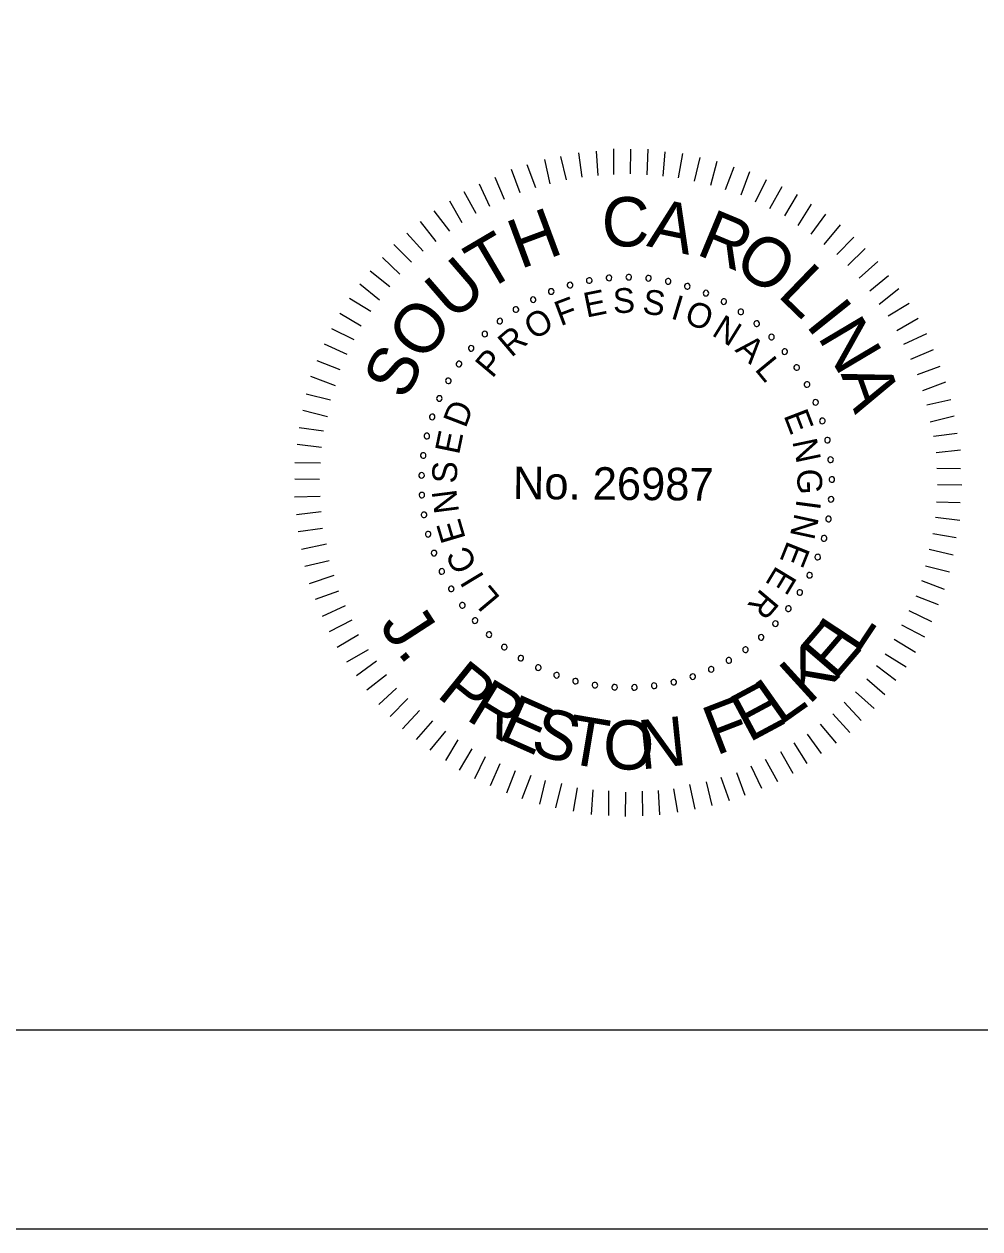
# Model space of a CAD drawing. Extents: x -125.5 to -89.4, y -5.1 to 16.9.
# Drawn here: x -102.74 to -100.338, y -5.066 to -2.039 of the extents above; entities that cross this region are included whole.
import ezdxf

# ---------------------------------------------------------------- set-up
doc = ezdxf.new("R2010")
doc.units = 0
for name, color, linetype in [('BR_BORDER LINES', 7, 'Continuous'), ('BR_TEXT', 7, 'Continuous'), ('Level 31', 7, 'Continuous')]:
    doc.layers.add(name, color=color, linetype=linetype)

msp = doc.modelspace()

# ---------------------------------------------------------------- linework, layer by layer
at = {"layer": 'BR_BORDER LINES'}
msp.add_line((-123.6994, -4.5662), (-90.0334, -4.5662), dxfattribs=at)
at = {"layer": 'BR_TEXT'}
for p, q in [((-101.2977, -2.419), (-101.3015, -2.3581)), ((-101.2582, -2.4168), (-101.2576, -2.3524)), ((-101.2161, -2.4146), (-101.2156, -2.3528)), ((-101.1741, -2.4175), (-101.1718, -2.3531)), ((-101.1338, -2.4204), (-101.129, -2.3595)), ((-101.418, -2.4404), (-101.4312, -2.3793)), ((-101.3767, -2.4304), (-101.3908, -2.3711)), ((-101.3372, -2.423), (-101.3461, -2.362)), ((-101.0952, -2.425), (-101.0844, -2.3642)), ((-101.0549, -2.4331), (-101.0407, -2.374)), ((-101.0138, -2.4437), (-100.9979, -2.3829)), ((-101.4937, -2.4629), (-101.5147, -2.4044)), ((-101.4541, -2.4504), (-101.476, -2.3927)), ((-100.977, -2.4543), (-100.9551, -2.397)), ((-100.9376, -2.4675), (-100.9157, -2.4093)), ((-101.5695, -2.4966), (-101.5957, -2.4406)), ((-101.5325, -2.4798), (-101.556, -2.4238)), ((-100.9017, -2.485), (-100.8738, -2.4294)), ((-100.8658, -2.5024), (-100.8345, -2.4469)), ((-101.604, -2.5144), (-101.6344, -2.46)), ((-100.8282, -2.5208), (-100.796, -2.467)), ((-101.6704, -2.5593), (-101.7095, -2.5083)), ((-101.6394, -2.5381), (-101.6698, -2.4838)), ((-100.795, -2.5451), (-100.761, -2.4913)), ((-101.7041, -2.5847), (-101.744, -2.5346)), ((-100.7617, -2.5668), (-100.7252, -2.5165)), ((-101.7369, -2.6094), (-101.7786, -2.5644)), ((-100.7293, -2.5928), (-100.6886, -2.5434)), ((-101.7663, -2.6366), (-101.8106, -2.5925)), ((-100.6977, -2.618), (-100.6545, -2.5737)), ((-100.6697, -2.6456), (-100.6264, -2.6022)), ((-101.7958, -2.6673), (-101.8392, -2.6248)), ((-101.8209, -2.6988), (-101.8704, -2.6598)), ((-100.6416, -2.6768), (-100.594, -2.6351)), ((-101.8469, -2.732), (-101.8964, -2.6922)), ((-100.6144, -2.7088), (-100.5677, -2.6705)), ((-100.5906, -2.7424), (-100.5414, -2.7033)), ((-101.8686, -2.761), (-101.9224, -2.728)), ((-100.5686, -2.7718), (-100.516, -2.7396)), ((-101.893, -2.7977), (-101.9467, -2.7656)), ((-100.5466, -2.8089), (-100.4931, -2.7776)), ((-101.9104, -2.8319), (-101.9668, -2.804)), ((-101.9279, -2.8687), (-101.9852, -2.8433)), ((-100.5288, -2.8433), (-100.4711, -2.8164)), ((-100.5111, -2.8804), (-100.4543, -2.856)), ((-101.9454, -2.9072), (-102.0035, -2.8852)), ((-100.4943, -2.9192), (-100.4374, -2.8982)), ((-101.9577, -2.9474), (-102.0193, -2.9246)), ((-100.4809, -2.9596), (-100.4232, -2.9378)), ((-101.97, -2.9833), (-102.0308, -2.9682)), ((-100.4708, -2.9957), (-100.4107, -2.9816)), ((-101.9772, -3.0253), (-102.0397, -3.0094)), ((-100.4626, -3.0378), (-100.4024, -3.0229)), ((-101.9878, -3.0613), (-102.0487, -3.0531)), ((-100.4543, -3.074), (-100.3951, -3.0667)), ((-101.9925, -3.1024), (-102.0542, -3.0951)), ((-100.4478, -3.1152), (-100.3868, -3.1088)), ((-101.9954, -3.1419), (-102.0597, -3.1414)), ((-100.4464, -3.1547), (-100.3863, -3.1552)), ((-101.9974, -3.183), (-102.06, -3.1825)), ((-100.4442, -3.1959), (-100.3833, -3.1964)), ((-101.9961, -3.226), (-102.0604, -3.2272)), ((-100.4471, -3.2388), (-100.3871, -3.241)), ((-101.9938, -3.2646), (-102.0556, -3.2718)), ((-100.4492, -3.2774), (-100.3883, -3.2856)), ((-101.9898, -3.3058), (-102.0509, -3.3148)), ((-100.4564, -3.3185), (-100.3972, -3.3284)), ((-101.9799, -3.3454), (-102.0426, -3.3586)), ((-100.4653, -3.3579), (-100.4053, -3.3721)), ((-101.9733, -3.3875), (-102.0344, -3.4016)), ((-100.4742, -3.3999), (-100.4143, -3.415)), ((-101.9616, -3.4245), (-102.0236, -3.4454)), ((-100.4848, -3.4367), (-100.4275, -3.4586)), ((-101.95, -3.4632), (-102.0085, -3.4842)), ((-100.4989, -3.4752), (-100.4424, -3.4971)), ((-101.9331, -3.5003), (-101.9908, -3.5272)), ((-101.9162, -3.5364), (-101.9731, -3.566)), ((-100.5163, -3.512), (-100.4599, -3.5399)), ((-100.5346, -3.5479), (-100.4774, -3.5784)), ((-101.8994, -3.5735), (-101.9537, -3.6048)), ((-100.553, -3.5846), (-100.5, -3.6168)), ((-101.8756, -3.6106), (-101.93, -3.6419)), ((-100.5756, -3.6213), (-100.5235, -3.6535)), ((-101.8544, -3.6399), (-101.9045, -3.6764)), ((-100.5981, -3.6503), (-100.5495, -3.6876)), ((-101.829, -3.6736), (-101.8791, -3.7127)), ((-100.6224, -3.6836), (-100.5764, -3.7234)), ((-101.8043, -3.7073), (-101.8485, -3.7481)), ((-100.6502, -3.7168), (-100.6033, -3.7584)), ((-101.7754, -3.7333), (-101.8204, -3.7784)), ((-100.6787, -3.7423), (-100.6362, -3.7882)), ((-101.7465, -3.7636), (-101.7889, -3.8095)), ((-100.7073, -3.7721), (-100.6648, -3.8188)), ((-101.714, -3.7895), (-101.7548, -3.8364)), ((-100.7392, -3.7976), (-100.6993, -3.8452)), ((-101.6808, -3.8156), (-101.7207, -3.8633)), ((-101.6501, -3.8373), (-101.6814, -3.8894)), ((-100.8057, -3.8443), (-100.7727, -3.8969)), ((-100.772, -3.8231), (-100.7364, -3.8714)), ((-101.6151, -3.8599), (-101.6464, -3.9137)), ((-100.8393, -3.8663), (-100.808, -3.9206)), ((-101.5809, -3.8799), (-101.608, -3.9355)), ((-101.5442, -3.8974), (-101.5687, -3.953)), ((-100.9135, -3.9026), (-100.8865, -3.9586)), ((-100.8773, -3.8857), (-100.8468, -3.9418)), ((-101.5057, -3.9149), (-101.5276, -3.9713)), ((-101.4663, -3.9272), (-101.4891, -3.9854)), ((-100.9892, -3.9311), (-100.9682, -3.9897)), ((-100.9496, -3.9194), (-100.9286, -3.9763)), ((-101.4304, -3.9395), (-101.4446, -3.9986)), ((-101.3892, -3.9467), (-101.4044, -4.0084)), ((-101.3499, -3.9582), (-101.3598, -4.0165)), ((-101.3104, -3.9628), (-101.3152, -4.0246)), ((-101.271, -3.9657), (-101.2715, -4.0275)), ((-101.1466, -3.9642), (-101.1428, -4.026)), ((-101.1079, -3.9602), (-101.098, -4.0186)), ((-101.0675, -3.9494), (-101.0542, -4.0113)), ((-101.0262, -3.9429), (-101.0112, -4.0022)), ((-101.229, -3.9686), (-101.2295, -4.0296)), ((-101.1869, -3.9664), (-101.1857, -4.0282))]:
    msp.add_line(p, q, dxfattribs=at)
for centre, start, end in [((-101.3681, -2.6945), 16.1422, 196.1422), ((-101.3681, -2.6945), 196.1422, 16.1422), ((-101.3196, -2.6831), 10.6038, 190.6038), ((-101.3196, -2.6831), 190.6038, 10.6038), ((-101.2702, -2.6764), 5.0653, 185.0653), ((-101.2702, -2.6764), 185.0653, 5.0653), ((-101.2204, -2.6745), 359.5268, 179.5268), ((-101.2204, -2.6745), 179.5268, 359.5268), ((-101.1707, -2.6774), 173.9884, 353.9884), ((-101.1707, -2.6774), 353.9884, 173.9884), ((-101.1214, -2.6851), 168.4499, 348.4499), ((-101.1214, -2.6851), 348.4499, 168.4499), ((-101.0732, -2.6976), 342.9114, 162.9114), ((-101.4607, -2.7311), 27.2191, 207.2191), ((-101.4153, -2.7106), 21.6807, 201.6807), ((-101.4153, -2.7106), 201.6807, 21.6807), ((-101.0732, -2.6976), 162.9114, 342.9114), ((-101.0263, -2.7146), 157.373, 337.373), ((-101.0263, -2.7146), 337.373, 157.373), ((-101.5039, -2.7559), 32.7576, 212.7576), ((-101.5039, -2.7559), 212.7576, 32.7576), ((-101.4607, -2.7311), 207.2191, 27.2191), ((-100.9814, -2.736), 151.8345, 331.8345), ((-100.9814, -2.736), 331.8345, 151.8345), ((-100.9387, -2.7617), 326.2961, 146.2961), ((-101.5445, -2.7848), 38.2961, 218.2961), ((-101.5445, -2.7848), 218.2961, 38.2961), ((-100.9387, -2.7617), 146.2961, 326.2961), ((-100.8987, -2.7914), 320.7576, 140.7576), ((-101.5821, -2.8175), 43.8345, 223.8345), ((-101.5821, -2.8175), 223.8345, 43.8345), ((-100.8987, -2.7914), 140.7576, 320.7576), ((-100.8617, -2.8249), 135.2191, 315.2191), ((-100.8617, -2.8249), 315.2191, 135.2191), ((-101.6164, -2.8536), 49.373, 229.373), ((-101.6164, -2.8536), 229.373, 49.373), ((-100.8282, -2.8617), 129.6807, 309.6807), ((-100.8282, -2.8617), 309.6807, 129.6807), ((-101.6471, -2.8929), 54.9114, 234.9114), ((-101.6471, -2.8929), 234.9114, 54.9114), ((-100.7983, -2.9016), 124.1422, 304.1422), ((-100.7983, -2.9016), 304.1422, 124.1422), ((-101.6738, -2.935), 60.4499, 240.4499), ((-101.6738, -2.935), 240.4499, 60.4499), ((-100.7724, -2.9442), 118.6038, 298.6038), ((-100.7724, -2.9442), 298.6038, 118.6038), ((-101.6964, -2.9794), 65.9884, 245.9884), ((-101.6964, -2.9794), 245.9884, 65.9884), ((-100.7508, -2.9891), 113.0653, 293.0653), ((-100.7508, -2.9891), 293.0653, 113.0653), ((-101.7145, -3.0258), 71.5268, 251.5268), ((-101.7145, -3.0258), 251.5268, 71.5268), ((-100.7336, -3.0359), 107.5268, 287.5268), ((-100.7336, -3.0359), 287.5268, 107.5268), ((-101.7281, -3.0738), 77.0653, 257.0653), ((-101.7281, -3.0738), 257.0653, 77.0653), ((-100.721, -3.0841), 101.9884, 281.9884), ((-100.721, -3.0841), 281.9884, 101.9884), ((-101.737, -3.1228), 82.6038, 262.6038), ((-101.737, -3.1228), 262.6038, 82.6038), ((-100.7131, -3.1333), 96.4499, 276.4499), ((-100.7131, -3.1333), 276.4499, 96.4499), ((-101.7411, -3.1724), 88.1422, 268.1422), ((-101.7411, -3.1724), 268.1422, 88.1422), ((-100.71, -3.183), 90.9114, 270.9114), ((-100.71, -3.183), 270.9114, 90.9114), ((-101.7404, -3.2223), 93.6807, 273.6807), ((-101.7404, -3.2223), 273.6807, 93.6807), ((-100.7118, -3.2328), 85.373, 265.373), ((-100.7118, -3.2328), 265.373, 85.373), ((-101.7349, -3.2718), 99.2191, 279.2191), ((-101.7349, -3.2718), 279.2191, 99.2191), ((-100.7183, -3.2822), 79.8345, 259.8345), ((-100.7183, -3.2822), 259.8345, 79.8345), ((-101.7246, -3.3206), 104.7576, 284.7576), ((-101.7246, -3.3206), 284.7576, 104.7576), ((-100.7295, -3.3308), 74.2961, 254.2961), ((-100.7295, -3.3308), 254.2961, 74.2961), ((-101.7097, -3.3681), 110.2961, 290.2961), ((-101.7097, -3.3681), 290.2961, 110.2961), ((-100.7454, -3.378), 68.7576, 248.7576), ((-100.7454, -3.378), 248.7576, 68.7576), ((-101.6903, -3.414), 115.8345, 295.8345), ((-101.6903, -3.414), 295.8345, 115.8345), ((-100.7658, -3.4235), 63.2191, 243.2191), ((-100.7658, -3.4235), 243.2191, 63.2191), ((-101.6665, -3.4578), 301.373, 121.373), ((-101.6665, -3.4578), 121.373, 301.373), ((-100.7904, -3.4668), 57.6807, 237.6807), ((-100.7904, -3.4668), 237.6807, 57.6807), ((-101.6386, -3.4991), 126.9114, 306.9114), ((-101.6386, -3.4991), 306.9114, 126.9114), ((-100.8192, -3.5075), 52.1422, 232.1422), ((-100.8192, -3.5075), 232.1422, 52.1422), ((-101.6069, -3.5375), 132.4499, 312.4499), ((-101.6069, -3.5375), 312.4499, 132.4499), ((-100.8517, -3.5452), 46.6038, 226.6038), ((-100.8517, -3.5452), 226.6038, 46.6038), ((-101.5716, -3.5727), 137.9884, 317.9884), ((-101.5716, -3.5727), 317.9884, 137.9884), ((-101.5331, -3.6043), 143.5268, 323.5268), ((-101.5331, -3.6043), 323.5268, 143.5268), ((-100.8877, -3.5797), 41.0653, 221.0653), ((-100.8877, -3.5797), 221.0653, 41.0653), ((-101.4917, -3.632), 149.0653, 329.0653), ((-101.4917, -3.632), 329.0653, 149.0653), ((-100.9688, -3.6374), 29.9884, 209.9884), ((-100.9269, -3.6105), 35.5268, 215.5268), ((-100.9269, -3.6105), 215.5268, 35.5268), ((-101.4478, -3.6556), 154.6038, 334.6038), ((-101.4478, -3.6556), 334.6038, 154.6038), ((-101.0132, -3.6601), 24.4499, 204.4499), ((-101.0132, -3.6601), 204.4499, 24.4499), ((-100.9688, -3.6374), 209.9884, 29.9884), ((-101.4018, -3.6749), 160.1422, 340.1422), ((-101.4018, -3.6749), 340.1422, 160.1422), ((-101.3542, -3.6896), 165.6807, 345.6807), ((-101.3542, -3.6896), 345.6807, 165.6807), ((-101.3054, -3.6997), 351.2191, 171.2191), ((-101.1074, -3.6921), 13.373, 193.373), ((-101.1074, -3.6921), 193.373, 13.373), ((-101.0595, -3.6784), 18.9114, 198.9114), ((-101.0595, -3.6784), 198.9114, 18.9114), ((-101.3054, -3.6997), 171.2191, 351.2191), ((-101.2559, -3.705), 356.7576, 176.7576), ((-101.2559, -3.705), 176.7576, 356.7576), ((-101.2061, -3.7055), 2.2961, 182.2961), ((-101.2061, -3.7055), 182.2961, 2.2961), ((-101.1564, -3.7012), 7.8345, 187.8345), ((-101.1564, -3.7012), 187.8345, 7.8345)]:
    msp.add_arc(centre, 0.00701, start, end, dxfattribs=at)
at = {"layer": 'Level 31'}
msp.add_lwpolyline([(-125.5328, -5.0661), (-89.5328, -5.0661), (-89.5328, 16.9339), (-125.5328, 16.9339)], close=True, dxfattribs=at)

# ---------------------------------------------------------------- texts
at = {"layer": 'BR_TEXT'}
for s, height, rotation, p in [('C', 0.1241, 359.5482, (-101.2889, -2.5969)), ('H', 0.1241, 20.3637, (-101.4933, -2.6552)), ('A', 0.1241, 348.1981, (-101.1775, -2.5961)), ('R', 0.1241, 337.4344, (-101.0542, -2.616)), ('T', 0.1241, 30.4992, (-101.5812, -2.7128)), ('O', 0.1239, 326.5869, (-100.962, -2.6528)), ('U', 0.1241, 40.8022, (-101.6624, -2.7875)), ('L', 0.1241, 315.9488, (-100.8494, -2.7205)), ('F', 0.0622, 20.6127, (-101.392, -2.7981)), ('E', 0.0622, 11.4103, (-101.3269, -2.7764)), ('S', 0.0622, 2.208, (-101.2591, -2.7654)), ('S', 0.0622, 352.6608, (-101.1878, -2.7657)), ('I', 0.0622, 343.1136, (-101.1175, -2.7777)), ('O', 0.1241, 52.0267, (-101.7369, -2.8914)), ('O', 0.0622, 338.4392, (-101.0841, -2.7878)), ('I', 0.1241, 308.6613, (-100.778, -2.7948)), ('O', 0.0622, 30.8477, (-101.4594, -2.8341)), ('N', 0.0622, 328.2042, (-101.0145, -2.8192)), ('N', 0.1241, 300.7037, (-100.7474, -2.8242)), ('R', 0.0622, 40.3949, (-101.5156, -2.878)), ('A', 0.0622, 318.657, (-100.9555, -2.8592)), ('S', 0.1239, 63.2511, (-101.7823, -2.9871)), ('P', 0.0622, 49.9421, (-101.5636, -2.9306)), ('L', 0.0622, 309.4546, (-100.9057, -2.9066)), ('A', 0.1241, 289.4792, (-100.6882, -2.9172)), ('D', 0.0622, 69.0364, (-101.6306, -3.0559)), ('E', 0.0622, 291.049, (-100.8319, -3.0219)), ('E', 0.0622, 78.2388, (-101.6472, -3.1226)), ('N', 0.0622, 281.8466, (-100.8097, -3.0869)), ('S', 0.0622, 87.786, (-101.6529, -3.1936)), ('No. 26987', 0.08175, 359.5268, (-101.5118, -3.232)), ('G', 0.0622, 272.2995, (-100.7979, -3.1572)), ('N', 0.0622, 97.3332, (-101.6467, -3.2646)), ('I', 0.0622, 262.4084, (-100.7983, -3.231)), ('E', 0.0622, 106.5355, (-101.6297, -3.3312)), ('N', 0.0622, 257.7339, (-100.8028, -3.2656)), ('C', 0.0622, 116.4266, (-101.5998, -3.3987)), ('E', 0.0622, 248.1867, (-100.8209, -3.3346)), ('I', 0.0622, 121.1011, (-101.5818, -3.4285)), ('E', 0.0622, 238.9844, (-100.8488, -3.3973)), ('L', 0.0622, 129.9595, (-101.5411, -3.4807)), ('R', 0.0622, 229.782, (-100.8865, -3.4548)), ('J', 0.1236, 302.9559, (-101.849, -3.5492)), ('E', 0.1236, 49.3639, (-100.703, -3.6911)), ('L', 0.1236, 56.4247, (-100.6455, -3.6233)), ('K', 0.1236, 42.3031, (-100.7683, -3.7512)), ('.', 0.1236, 309.3974, (-101.8049, -3.6172)), ('P', 0.1236, 321.1035, (-101.7065, -3.7264)), ('R', 0.1236, 328.5359, (-101.6332, -3.7844)), ('E', 0.1236, 28.1814, (-100.9186, -3.8452)), ('L', 0.1236, 35.2422, (-100.8406, -3.8028)), ('E', 0.1236, 335.9684, (-101.5531, -3.8325)), ('F', 0.1236, 21.1206, (-101.0013, -3.8776)), ('S', 0.1236, 343.0292, (-101.4718, -3.8682)), ('T', 0.1236, 350.4617, (-101.3821, -3.8947)), ('N', 0.1236, 5.8221, (-101.1902, -3.9118)), ('O', 0.1236, 358.1419, (-101.2867, -3.9097))]:
    msp.add_text(s, height=height, rotation=rotation, dxfattribs=at).set_placement(p)

doc.saveas('drawing.dxf')
